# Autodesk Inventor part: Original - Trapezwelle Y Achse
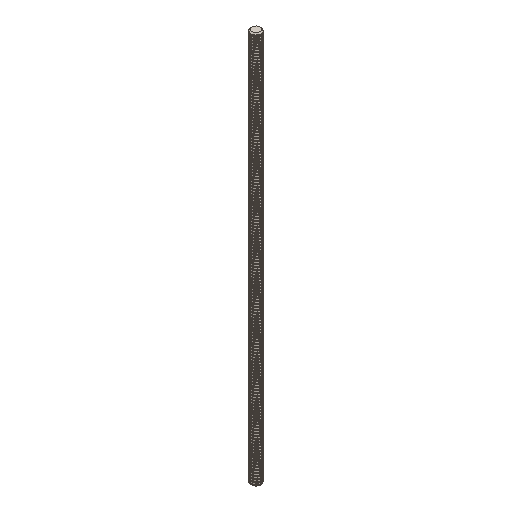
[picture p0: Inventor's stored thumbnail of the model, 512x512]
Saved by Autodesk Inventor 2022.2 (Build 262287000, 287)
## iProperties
Created: 2024-09
Part Number: Original - Trapezwelle Y Achse
Material: Generico
Document SubType Name: Modeling
Designer: 18907419
Density: 1 g/cm^3
Appearance: Default
Author: 18907419
Revision Number: ANY
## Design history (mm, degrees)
feature "Schnitt-Rotation1"
node "Solido1"
